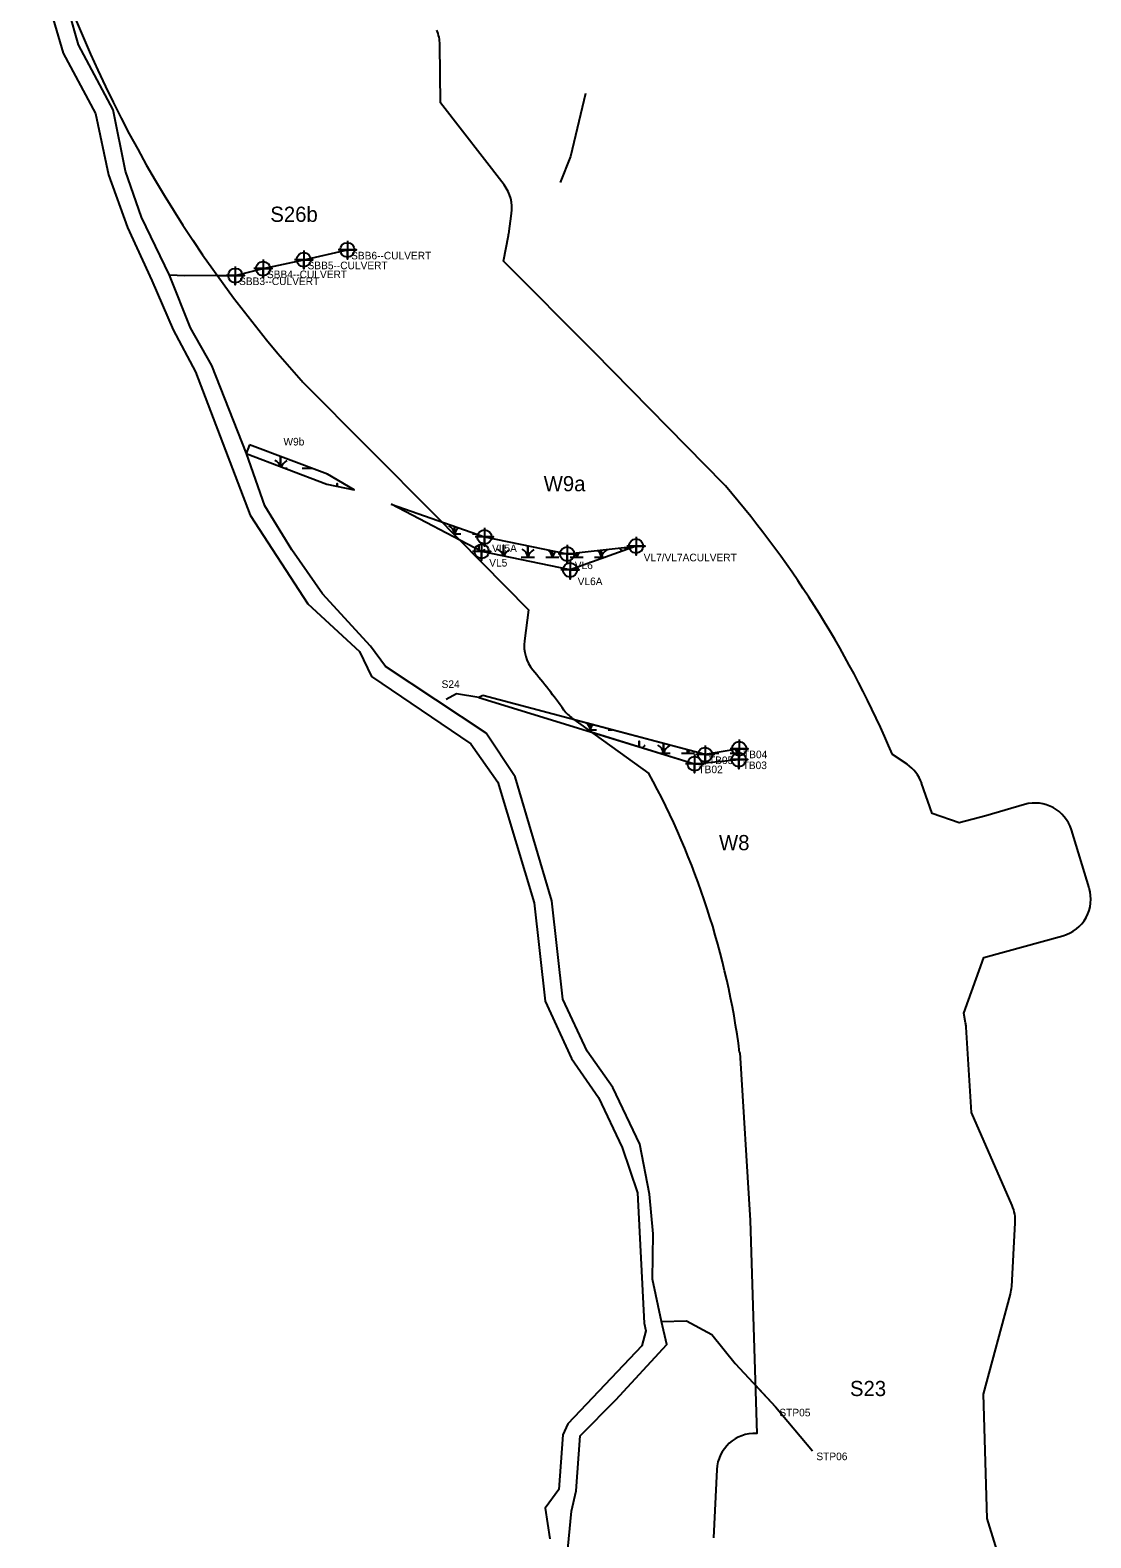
# Model space of a CAD drawing. Extents: x 1253697 to 1278588, y 912189 to 981699.
# Drawn here: x 1262263 to 1263659, y 923116 to 925101 of the extents above; entities that cross this region are included whole.
import ezdxf

# ---------------------------------------------------------------- set-up
doc = ezdxf.new("R2010")
doc.units = 0
for name, color, linetype in [('Default', 7, 'Continuous'), ('Exist Environmental Wetland Boundary', 7, 'Continuous'), ('Exist Environmental Wetland Boundary Cogo Comment', 7, 'Continuous'), ('Exist Environmental Wetland Boundary Cogo Number', 7, 'Continuous'), ('Exist Environmental Wetland Boundary Cogo Point CELL', 7, 'Continuous'), ('Exist Hydro Jurisdictional Stream or Body of Water Mitigable', 7, 'Continuous'), ('Exist Hydro Jurisdictional Stream or Body of Water Mitigable Cogo Comment', 7, 'Continuous'), ('Exist Hydro Jurisdictional Stream or Body of Water Mitigable Cogo Number', 7, 'Continuous'), ('Exist Hydro Jurisdictional Stream or Body of Water Mitigable Cogo Point CELL', 7, 'Continuous'), ('Exist Hydro Swamp or Marsh', 7, 'Continuous')]:
    doc.layers.add(name, color=color, linetype=linetype)

msp = doc.modelspace()

# ---------------------------------------------------------------- linework, layer by layer
at = {"layer": 'Default'}
for p, q in [((1262892.7, 924832.7), (1262896.6, 924859.4)), ((1262892.7, 924832.7), (1262896.6, 924859.4)), ((1262892.7, 924832.7), (1262896.6, 924859.4)), ((1262892.7, 924832.7), (1262896.6, 924859.4)), ((1263175.9, 924503.2), (1263005.2, 924677.1)), ((1263175.9, 924503.2), (1263005.2, 924677.1)), ((1263175.9, 924503.2), (1263005.2, 924677.1)), ((1263175.9, 924503.2), (1263005.2, 924677.1)), ((1262976.8, 924194.6), (1263077.2, 924122.4)), ((1262976.8, 924194.6), (1263077.2, 924122.4)), ((1262976.8, 924194.6), (1263077.2, 924122.4)), ((1262976.8, 924194.6), (1263077.2, 924122.4)), ((1263417.2, 924134.4), (1263398.1, 924147.3)), ((1263417.2, 924134.4), (1263398.1, 924147.3)), ((1263417.2, 924134.4), (1263398.1, 924147.3)), ((1263417.2, 924134.4), (1263398.1, 924147.3)), ((1263656.9, 923971.5), (1263633.5, 924048)), ((1263656.9, 923971.5), (1263633.5, 924048)), ((1263656.9, 923971.5), (1263633.5, 924048)), ((1263656.9, 923971.5), (1263633.5, 924048)), ((1263555, 923446.9), (1263559.6, 923530.5)), ((1263555, 923446.9), (1263559.6, 923530.5)), ((1263555, 923446.9), (1263559.6, 923530.5)), ((1263555, 923446.9), (1263559.6, 923530.5)), ((1263166.7, 923205.8), (1263162.4, 923115.9)), ((1263166.7, 923205.8), (1263162.4, 923115.9)), ((1263166.7, 923205.8), (1263162.4, 923115.9)), ((1263166.7, 923205.8), (1263162.4, 923115.9))]:
    msp.add_line(p, q, dxfattribs=at)
for points in [[(1262886.6, 924897.1), (1262803, 925005.3), (1262802.1, 925081.7)], [(1262886.6, 924897.1), (1262803, 925005.3), (1262802.1, 925081.7)], [(1262886.6, 924897.1), (1262803, 925005.3), (1262802.1, 925081.7)], [(1262886.6, 924897.1), (1262803, 925005.3), (1262802.1, 925081.7)], [(1263005, 924677.3), (1262886.1, 924796.9), (1262892.4, 924830.6)], [(1263005, 924677.3), (1262886.1, 924796.9), (1262892.4, 924830.6)], [(1263005, 924677.3), (1262886.1, 924796.9), (1262892.4, 924830.6)], [(1263005, 924677.3), (1262886.1, 924796.9), (1262892.4, 924830.6)], [(1262621.3, 924638), (1262795.9, 924462.2), (1262918.6, 924337.6), (1262913.5, 924296.7)], [(1262621.3, 924638), (1262795.9, 924462.2), (1262918.6, 924337.6), (1262913.5, 924296.7)], [(1262621.3, 924638), (1262795.9, 924462.2), (1262918.6, 924337.6), (1262913.5, 924296.7)], [(1262621.3, 924638), (1262795.9, 924462.2), (1262918.6, 924337.6), (1262913.5, 924296.7)], [(1263571.8, 924081.4), (1263520.7, 924066.6), (1263485.6, 924057.1), (1263450.3, 924069.7), (1263436.4, 924109.4)], [(1263571.8, 924081.4), (1263520.7, 924066.6), (1263485.6, 924057.1), (1263450.3, 924069.7), (1263436.4, 924109.4)], [(1263571.8, 924081.4), (1263520.7, 924066.6), (1263485.6, 924057.1), (1263450.3, 924069.7), (1263436.4, 924109.4)], [(1263571.8, 924081.4), (1263520.7, 924066.6), (1263485.6, 924057.1), (1263450.3, 924069.7), (1263436.4, 924109.4)], [(1263494.2, 923794), (1263492, 923806.7), (1263518.1, 923879.9), (1263622.4, 923908.6)], [(1263494.2, 923794), (1263492, 923806.7), (1263518.1, 923879.9), (1263622.4, 923908.6)], [(1263494.2, 923794), (1263492, 923806.7), (1263518.1, 923879.9), (1263622.4, 923908.6)], [(1263494.2, 923794), (1263492, 923806.7), (1263518.1, 923879.9), (1263622.4, 923908.6)], [(1263555.5, 923553.3), (1263502.1, 923675.7), (1263494.9, 923788.4)], [(1263555.5, 923553.3), (1263502.1, 923675.7), (1263494.9, 923788.4)], [(1263555.5, 923553.3), (1263502.1, 923675.7), (1263494.9, 923788.4)], [(1263555.5, 923553.3), (1263502.1, 923675.7), (1263494.9, 923788.4)], [(1263196.8, 923754.9), (1263210.6, 923533.7), (1263219.2, 923253.3), (1263219.1, 923253.3)], [(1263196.8, 923754.9), (1263210.6, 923533.7), (1263219.2, 923253.3), (1263219.1, 923253.3)], [(1263196.8, 923754.9), (1263210.6, 923533.7), (1263219.2, 923253.3), (1263219.1, 923253.3)], [(1263196.8, 923754.9), (1263210.6, 923533.7), (1263219.2, 923253.3), (1263219.1, 923253.3)], [(1263542.7, 923076), (1263522.8, 923141.4), (1263517.8, 923304.9), (1263553.3, 923436.7)], [(1263542.7, 923076), (1263522.8, 923141.4), (1263517.8, 923304.9), (1263553.3, 923436.7)], [(1263542.7, 923076), (1263522.8, 923141.4), (1263517.8, 923304.9), (1263553.3, 923436.7)], [(1263542.7, 923076), (1263522.8, 923141.4), (1263517.8, 923304.9), (1263553.3, 923436.7)]]:
    msp.add_lwpolyline(points, dxfattribs=at)
for centre, radius, start, end in [((1263850.1, 925739.1), 1650, 195.8394, 221.7719), ((1263850.1, 925739.1), 1650, 195.8394, 221.7719), ((1263850.1, 925739.1), 1650, 195.8394, 221.7719), ((1263850.1, 925739.1), 1650, 195.8394, 221.7719), ((1262752.1, 925081.2), 50, 0.6306, 23.2408), ((1262752.1, 925081.2), 50, 0.6306, 23.2408), ((1262752.1, 925081.2), 50, 0.6306, 23.2408), ((1262752.1, 925081.2), 50, 0.6306, 23.2408), ((1262847.1, 924866.5), 50, 351.8594, 37.7047), ((1262847.1, 924866.5), 50, 351.8594, 37.7047), ((1262847.1, 924866.5), 50, 351.8594, 37.7047), ((1262847.1, 924866.5), 50, 351.8594, 37.7047), ((1262843.3, 924839.8), 50, 349.3922, 351.8594), ((1262843.3, 924839.8), 50, 349.3922, 351.8594), ((1262843.3, 924839.8), 50, 349.3922, 351.8594), ((1262843.3, 924839.8), 50, 349.3922, 351.8594), ((1262969.5, 924642.1), 50, 44.4564, 44.8541), ((1262969.5, 924642.1), 50, 44.4564, 44.8541), ((1262969.5, 924642.1), 50, 44.4564, 44.8541), ((1262969.5, 924642.1), 50, 44.4564, 44.8541), ((1262656.8, 924673.3), 50, 221.7719, 224.8031), ((1262656.8, 924673.3), 50, 221.7719, 224.8031), ((1262656.8, 924673.3), 50, 221.7719, 224.8031), ((1262656.8, 924673.3), 50, 221.7719, 224.8031), ((1263140.2, 924468.2), 50, 40.7692, 44.4564), ((1263140.2, 924468.2), 50, 40.7692, 44.4564), ((1263140.2, 924468.2), 50, 40.7692, 44.4564), ((1263140.2, 924468.2), 50, 40.7692, 44.4564), ((1262155.6, 923619.2), 1350, 23.0266, 40.7692), ((1262155.6, 923619.2), 1350, 23.0266, 40.7692), ((1262155.6, 923619.2), 1350, 23.0266, 40.7692), ((1262155.6, 923619.2), 1350, 23.0266, 40.7692), ((1262963.1, 924290.5), 50, 172.875, 219.7361), ((1262963.1, 924290.5), 50, 172.875, 219.7361), ((1262963.1, 924290.5), 50, 172.875, 219.7361), ((1262963.1, 924290.5), 50, 172.875, 219.7361), ((1262155.6, 923619.2), 1000, 35.9164, 39.7361), ((1262155.6, 923619.2), 1000, 35.9164, 39.7361), ((1262155.6, 923619.2), 1000, 35.9164, 39.7361), ((1262155.6, 923619.2), 1000, 35.9164, 39.7361), ((1263006, 924235.2), 50, 215.9164, 234.2875), ((1263006, 924235.2), 50, 215.9164, 234.2875), ((1263006, 924235.2), 50, 215.9164, 234.2875), ((1263006, 924235.2), 50, 215.9164, 234.2875), ((1262155.6, 923619.2), 1050, 7.4247, 28.6323), ((1262155.6, 923619.2), 1050, 7.4247, 28.6323), ((1262155.6, 923619.2), 1050, 7.4247, 28.6323), ((1262155.6, 923619.2), 1050, 7.4247, 28.6323), ((1263389.2, 924093), 50, 19.1858, 56.0015), ((1263389.2, 924093), 50, 19.1858, 56.0015), ((1263389.2, 924093), 50, 19.1858, 56.0015), ((1263389.2, 924093), 50, 19.1858, 56.0015), ((1263585.7, 924033.3), 50, 17.0094, 106.1453), ((1263585.7, 924033.3), 50, 17.0094, 106.1453), ((1263585.7, 924033.3), 50, 17.0094, 106.1453), ((1263585.7, 924033.3), 50, 17.0094, 106.1453), ((1263609.1, 923956.8), 50, 285.4055, 17.0094), ((1263609.1, 923956.8), 50, 285.4055, 17.0094), ((1263609.1, 923956.8), 50, 285.4055, 17.0094), ((1263609.1, 923956.8), 50, 285.4055, 17.0094), ((1263445, 923785.2), 50, 3.6489, 10.0336), ((1263445, 923785.2), 50, 3.6489, 10.0336), ((1263445, 923785.2), 50, 3.6489, 10.0336), ((1263445, 923785.2), 50, 3.6489, 10.0336), ((1263509.7, 923533.3), 50, 356.7933, 23.5877), ((1263509.7, 923533.3), 50, 356.7933, 23.5877), ((1263509.7, 923533.3), 50, 356.7933, 23.5877), ((1263509.7, 923533.3), 50, 356.7933, 23.5877), ((1263505, 923449.7), 50, 344.9162, 356.7933), ((1263505, 923449.7), 50, 344.9162, 356.7933), ((1263505, 923449.7), 50, 344.9162, 356.7933), ((1263505, 923449.7), 50, 344.9162, 356.7933), ((1263216.7, 923203.3), 50, 87.2304, 177.2304), ((1263216.7, 923203.3), 50, 87.2304, 177.2304), ((1263216.7, 923203.3), 50, 87.2304, 177.2304), ((1263216.7, 923203.3), 50, 87.2304, 177.2304)]:
    msp.add_arc(centre, radius, start, end, dxfattribs=at)
at = {"layer": 'Exist Environmental Wetland Boundary'}
for points in [[(1262551.7, 924554.8), (1262547.3, 924543.5), (1262653.1, 924503), (1262689.2, 924495.8), (1262654.1, 924516.5)], [(1262737.8, 924476.6), (1262860.8, 924433.7), (1262969.7, 924411.3), (1263060.4, 924421.6), (1262973.5, 924390.2), (1262857.1, 924414.7)], [(1262858.6, 924225.1), (1262853.5, 924222.3), (1263137.5, 924135.1), (1263195.7, 924140.5), (1263196.2, 924154.8), (1263151.3, 924147.1)]]:
    msp.add_lwpolyline(points, close=True, dxfattribs=at)
msp.add_lwpolyline([(1263001.5, 924176.9), (1263137.5, 924135.1), (1263195.7, 924140.5), (1263196.2, 924154.8), (1263151.3, 924147.1), (1262979, 924193)], dxfattribs=at)
at = {"layer": 'Exist Environmental Wetland Boundary Cogo Point CELL'}
for points in [[(1262860.8, 924445.7), (1262860.8, 924421.7), (1262860.8, 924433.7), (1262872.8, 924433.7), (1262848.8, 924433.7)], [(1262857.1, 924426.7), (1262857.1, 924402.7), (1262857.1, 924414.7), (1262869.1, 924414.7), (1262845.1, 924414.7)], [(1262969.7, 924423.3), (1262969.7, 924399.3), (1262969.7, 924411.3), (1262981.7, 924411.3), (1262957.7, 924411.3)], [(1263060.4, 924433.6), (1263060.4, 924409.6), (1263060.4, 924421.6), (1263072.4, 924421.6), (1263048.4, 924421.6)], [(1262973.5, 924402.2), (1262973.5, 924378.2), (1262973.5, 924390.2), (1262985.5, 924390.2), (1262961.5, 924390.2)], [(1263151.3, 924159.1), (1263151.3, 924135.1), (1263151.3, 924147.1), (1263163.3, 924147.1), (1263139.3, 924147.1)], [(1263196.2, 924166.8), (1263196.2, 924142.8), (1263196.2, 924154.8), (1263208.2, 924154.8), (1263184.2, 924154.8)], [(1263137.5, 924147.1), (1263137.5, 924123.1), (1263137.5, 924135.1), (1263149.5, 924135.1), (1263125.5, 924135.1)], [(1263195.7, 924152.5), (1263195.7, 924128.5), (1263195.7, 924140.5), (1263207.7, 924140.5), (1263183.7, 924140.5)]]:
    msp.add_lwpolyline(points, dxfattribs=at)
for centre in [(1262860.8, 924433.7), (1262857.1, 924414.7), (1262969.7, 924411.3), (1263060.4, 924421.6), (1262973.5, 924390.2), (1263151.3, 924147.1), (1263196.2, 924154.8), (1263137.5, 924135.1), (1263195.7, 924140.5)]:
    msp.add_circle(centre, 9.38, dxfattribs=at)
at = {"layer": 'Exist Hydro Jurisdictional Stream or Body of Water Mitigable'}
for p, q in [((1262592.4, 924526.2), (1262592.4, 924539.6)), ((1262592.4, 924539.6), (1262592.4, 924526.2)), ((1262598.2, 924524), (1262601, 924524))]:
    msp.add_line(p, q, dxfattribs=at)
for points in [[(1262962.7, 923018.7), (1262975.4, 923151.1), (1262981.6, 923177.6), (1262987, 923250), (1263033.6, 923297.5), (1263100.8, 923370.5), (1263094, 923400.6), (1263082, 923456.5), (1263082.9, 923516.1), (1263078, 923568.2), (1263065.4, 923634.4), (1263030, 923708.9), (1262996.1, 923756.7), (1262963.8, 923825.1), (1262949.4, 923954.5), (1262901.3, 924117.7), (1262862.9, 924175.2), (1262730.5, 924263.3), (1262711, 924289.9), (1262647.4, 924358.6), (1262607.2, 924416.9), (1262571.9, 924474.5), (1262547.5, 924543.5), (1262501.9, 924659.6), (1262473.8, 924708.8), (1262446, 924778.3), (1262409.2, 924854.5), (1262388.2, 924915.1), (1262371.9, 924995.9), (1262326.4, 925081.5), (1262301, 925171.4)], [(1262278.4, 925164.8), (1262306.1, 925070.7), (1262348.6, 924991), (1262365.7, 924910.6), (1262390.8, 924840.9), (1262423.1, 924771.5), (1262451, 924706.3), (1262480.3, 924651.2), (1262552.3, 924462.5), (1262628.4, 924345.5), (1262696.5, 924283), (1262712.1, 924249.7), (1262842.7, 924161.1), (1262878.4, 924110.7), (1262926.2, 923951.8), (1262940.9, 923822.5), (1262975.3, 923746.9), (1263010.9, 923695.5), (1263042.1, 923629.8), (1263062.4, 923570.2), (1263071.2, 923398.4), (1263073.2, 923388.6), (1263073.2, 923388.6), (1263067.8, 923368.5), (1262970.6, 923266.1), (1262964.1, 923251.7), (1262958.7, 923179.3), (1262940.8, 923154.8), (1262946.9, 923114.4)], [(1262994, 925017.4), (1262974.2, 924934.4), (1262960.4, 924900.4)], [(1262509.2, 924777.6), (1262532.8, 924777.8), (1262569.4, 924786.9), (1262622.9, 924798.6), (1262680.3, 924811.6)], [(1262532.8, 924777.8), (1262466.5, 924777.3), (1262446, 924778.3)], [(1262621, 924524), (1262629.6, 924524), (1262629.6, 924525.6)], [(1262629.6, 924525.6), (1262629.6, 924524), (1262634, 924524)], [(1262666.8, 924500.2), (1262666.8, 924504), (1262666.8, 924500.2)], [(1262853.5, 924222.3), (1262824, 924227.1), (1262810.5, 924219.8)], [(1263094, 923400.6), (1263126.8, 923401.5), (1263160, 923383.8), (1263191, 923345.5), (1263244.1, 923288.3)], [(1263217.3, 923317.1), (1263244.1, 923288.3), (1263292.8, 923230.6)]]:
    msp.add_lwpolyline(points, dxfattribs=at)
for centre, radius, start, end in [((1262580.2, 924523.1), 12.3, 15.4525, 67.535), ((1262610.7, 924517.9), 19.2, 122.1274, 155.4107), ((1262617.4, 924523.1), 12.3, 4.1403, 12.2998), ((1262647.9, 924517.9), 19.2, 157.0483, 161.6222)]:
    msp.add_arc(centre, radius, start, end, dxfattribs=at)
at = {"layer": 'Exist Hydro Jurisdictional Stream or Body of Water Mitigable Cogo Point CELL'}
for points in [[(1262680.3, 924823.6), (1262680.3, 924799.6), (1262680.3, 924811.6), (1262692.3, 924811.6), (1262668.3, 924811.6)], [(1262569.4, 924798.9), (1262569.4, 924774.9), (1262569.4, 924786.9), (1262581.4, 924786.9), (1262557.4, 924786.9)], [(1262622.9, 924810.6), (1262622.9, 924786.6), (1262622.9, 924798.6), (1262634.9, 924798.6), (1262610.9, 924798.6)], [(1262532.8, 924789.8), (1262532.8, 924765.8), (1262532.8, 924777.8), (1262544.8, 924777.8), (1262520.8, 924777.8)]]:
    msp.add_lwpolyline(points, dxfattribs=at)
for centre in [(1262680.3, 924811.6), (1262569.4, 924786.9), (1262622.9, 924798.6), (1262532.8, 924777.8)]:
    msp.add_circle(centre, 9.38, dxfattribs=at)
at = {"layer": 'Exist Hydro Swamp or Marsh'}
for p, q in [((1262844.9, 924437.7), (1262849.5, 924437.7)), ((1263046.7, 924416.6), (1263046.7, 924420)), ((1263046.7, 924420), (1263046.7, 924416.6)), ((1262894.1, 924406.9), (1262894.3, 924406.9)), ((1263023.5, 924179.7), (1263029, 924179.7)), ((1263161.9, 924148.9), (1263169.5, 924148.9))]:
    msp.add_line(p, q, dxfattribs=at)
for points in [[(1262820.1, 924437.7), (1262821.3, 924437.7), (1262821.3, 924447.5)], [(1262821.3, 924447.5), (1262821.3, 924437.7), (1262829.9, 924437.7)], [(1262853.5, 924416.5), (1262853.5, 924422.7), (1262853.5, 924416.5)], [(1262885.7, 924408.7), (1262885.7, 924422.7), (1262885.7, 924408.7)], [(1262909.3, 924406.9), (1262917.9, 924406.9), (1262917.9, 924422)], [(1262917.9, 924422), (1262917.9, 924406.9), (1262926.5, 924406.9)], [(1262941.5, 924406.9), (1262950.1, 924406.9), (1262950.1, 924415.3)], [(1262950.1, 924415.3), (1262950.1, 924406.9), (1262958.7, 924406.9)], [(1263005.9, 924406.9), (1263014.5, 924406.9), (1263014.5, 924416.4)], [(1263014.5, 924416.4), (1263014.5, 924406.9), (1263019.7, 924406.9)], [(1262973.7, 924406.9), (1262982.3, 924406.9), (1262982.3, 924412.7)], [(1262982.3, 924412.7), (1262982.3, 924406.9), (1262990.9, 924406.9)], [(1262997.6, 924179.7), (1262999.9, 924179.7), (1262999.9, 924187.4)], [(1262999.9, 924187.4), (1262999.9, 924179.7), (1263008.5, 924179.7)], [(1263064.3, 924157.6), (1263064.3, 924164.7), (1263064.3, 924157.6)], [(1263092.6, 924148.9), (1263096.5, 924148.9), (1263096.5, 924161.7)], [(1263096.5, 924161.7), (1263096.5, 924148.9), (1263105.1, 924148.9)], [(1263120.1, 924148.9), (1263128.7, 924148.9), (1263128.7, 924153.1)], [(1263128.7, 924153.1), (1263128.7, 924148.9), (1263137.3, 924148.9)], [(1263184.5, 924148.9), (1263193.1, 924148.9), (1263193.1, 924154.3)], [(1263193.1, 924154.3), (1263193.1, 924148.9), (1263196, 924148.9)]]:
    msp.add_lwpolyline(points, dxfattribs=at)
for centre, radius, start, end in [((1262809, 924436.8), 12.3, 4.1403, 67.535), ((1262839.5, 924431.6), 19.2, 132.8524, 161.6222), ((1262871.7, 924400.8), 19.2, 122.1274, 134.9244), ((1262873.4, 924406), 12.3, 12.7814, 67.535), ((1262903.9, 924400.8), 19.2, 122.1274, 156.3734), ((1262905.6, 924406), 12.3, 4.1403, 67.535), ((1262936.1, 924400.8), 19.2, 122.1274, 161.6222), ((1262937.8, 924406), 12.3, 4.1403, 58.9466), ((1262968.3, 924400.8), 19.2, 135.2183, 161.6222), ((1263002.2, 924406), 12.3, 4.1403, 52.8353), ((1263032.7, 924400.8), 19.2, 122.1274, 161.6222), ((1263034.4, 924406), 12.3, 48.096, 67.535), ((1262970, 924406), 12.3, 4.1403, 31.8673), ((1263000.5, 924400.8), 19.2, 140.3665, 161.6222), ((1262987.6, 924178.8), 12.3, 4.1403, 54.5662), ((1263018.1, 924173.6), 19.2, 138.3019, 161.6222), ((1263082.5, 924142.8), 19.2, 122.1274, 135.8511), ((1263084.2, 924148), 12.3, 4.1403, 67.535), ((1263114.7, 924142.8), 19.2, 122.1274, 161.6222), ((1263116.4, 924148), 12.3, 4.1403, 26.1395), ((1263146.9, 924142.8), 19.2, 149.3204, 161.6222), ((1263180.8, 924148), 12.3, 4.1403, 29.0969), ((1263211.3, 924142.8), 19.2, 142.1163, 161.6222)]:
    msp.add_arc(centre, radius, start, end, dxfattribs=at)

# ---------------------------------------------------------------- texts
at = {"layer": 'Exist Environmental Wetland Boundary'}
msp.add_text('S24', height=10, dxfattribs=at).set_placement((1262804.4, 924234.8))
at = {"layer": 'Exist Environmental Wetland Boundary Cogo Comment'}
for s, p in [('VL5A', (1262870.8, 924413.7)), ('VL5', (1262867.1, 924394.7)), ('VL6', (1262979.7, 924391.3)), ('VL7/VL7ACULVERT', (1263070.4, 924401.6)), ('VL6A', (1262983.5, 924370.2)), ('TB05', (1263156.3, 924134.6)), ('TB03', (1263200.7, 924128)), ('TB04', (1263201.2, 924142.3)), ('TB02', (1263142.5, 924122.6))]:
    msp.add_text(s, height=10, dxfattribs=at).set_placement(p)
at = {"layer": 'Exist Environmental Wetland Boundary Cogo Number'}
for s, p in [('W9a', (1262938.8, 924493.8)), ('W8', (1263169.6, 924021.2))]:
    msp.add_text(s, height=20, dxfattribs=at).set_placement(p)
at = {"layer": 'Exist Hydro Jurisdictional Stream or Body of Water Mitigable'}
msp.add_text('W9b', height=10, dxfattribs=at).set_placement((1262596.2, 924554.1))
at = {"layer": 'Exist Hydro Jurisdictional Stream or Body of Water Mitigable Cogo Comment'}
for s, p in [('SBB5--CULVERT', (1262627.9, 924786.1)), ('SBB6--CULVERT', (1262685.3, 924799.1)), ('SBB3--CULVERT', (1262537.8, 924765.3)), ('SBB4--CULVERT', (1262574.4, 924774.4)), ('STP05', (1263249.1, 923275.8)), ('STP06', (1263297.8, 923218.1))]:
    msp.add_text(s, height=10, dxfattribs=at).set_placement(p)
at = {"layer": 'Exist Hydro Jurisdictional Stream or Body of Water Mitigable Cogo Number'}
for s, p in [('S26b', (1262578.9, 924848.5)), ('S23', (1263342, 923302.5))]:
    msp.add_text(s, height=20, dxfattribs=at).set_placement(p)

doc.saveas('drawing.dxf')
